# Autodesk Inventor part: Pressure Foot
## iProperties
Shininess: 64.0
Length Units: 11272
Angle Units: 11279
Time Units: 11290
Mass Units: 11286
Length Display Precision: 3
Angle Display Precision: 2
Compacted: True
Part Number: Pressure Foot
Document SubType Name: Modeling
Created: 2003-08
Designer: FT User
Manufacturer: Standard
Standards Organization: Custom
Density: 0.0
Volumn: 0.0
Area: 0.0
PropertySet Name: Model Information
Control State: 0
Master: False
Checked Out: False
Author: FT User
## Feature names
1. Extrusion1
2. Extrusion2
3. Revolution1
